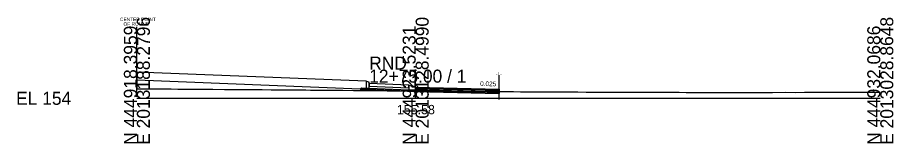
# Model space of a CAD drawing. Extents: x -26 to 163, y -10 to 7518.
# Drawn here: x -25.7 to 162.8, y 5490.3 to 5517.3 of the extents above; entities that cross this region are included whole.
import ezdxf

# ---------------------------------------------------------------- set-up
doc = ezdxf.new("R2010")
doc.units = 0
for name, color, linetype in [('Exist Cross Section Cell', 7, 'Continuous'), ('Exist XS Center Line Elevation Label', 7, 'Continuous'), ('Exist XS Ground Line', 7, 'Continuous'), ('Prop CMT Conc Surface', 7, 'Continuous'), ('Prop CMT Concrete Structures', 7, 'Continuous'), ('Prop CMT Pvmt Course 1', 7, 'Continuous'), ('Prop CMT Pvmt Course 1 CG', 7, 'Continuous'), ('Prop CMT Pvmt Course 2', 7, 'Continuous'), ('Prop CMT Pvmt Course 3', 7, 'Continuous'), ('Prop CMT Pvmt Surface', 7, 'Continuous'), ('Prop CMT Shear Line', 7, 'Continuous'), ('Prop CMT Shear Line Text', 7, 'Continuous'), ('Prop CMT Slope Grass', 7, 'Continuous'), ('Prop CMT Subgrade Earthwork', 7, 'Continuous'), ('Prop XS Earthwork Shape', 7, 'Continuous'), ('Prop XS SE Text', 7, 'Continuous')]:
    doc.layers.add(name, color=color, linetype=linetype)

msp = doc.modelspace()

# ---------------------------------------------------------------- linework, layer by layer
at = {"layer": 'Exist Cross Section Cell'}
for p, q in [((60, 5500), (60, 5506.16)), ((0, 5500), (60, 5500)), ((60, 5500), (160, 5500))]:
    msp.add_line(p, q, dxfattribs=at)
at = {"layer": 'Exist XS Ground Line'}
msp.add_lwpolyline([(0, 5502.05), (1.26, 5502.04), (2.71, 5502.03), (3.77, 5502.03), (5.03, 5502.02), (6.29, 5502.01), (7.37, 5502), (8.8, 5501.99), (10.5, 5501.98), (11.31, 5501.97), (13.27, 5501.96), (13.82, 5501.95), (16, 5501.94), (16.33, 5501.93), (18.83, 5501.92), (19.69, 5501.92), (21.51, 5501.9), (23.85, 5501.89), (25.84, 5501.87), (26.36, 5501.87), (26.98, 5501.86), (28.87, 5501.85), (29.73, 5501.84), (31.38, 5501.83), (32.47, 5501.82), (33.89, 5501.81), (35.06, 5501.8), (36.39, 5501.79), (37.39, 5501.78), (38.91, 5501.76), (39.7, 5501.76), (41.42, 5501.74), (42.01, 5501.74), (43.93, 5501.72), (44.33, 5501.72), (46.65, 5501.7), (49.08, 5501.68), (51.62, 5501.65), (53.85, 5501.63), (54.32, 5501.62), (56.29, 5501.61), (56.99, 5501.6), (58.74, 5501.59), (59.66, 5501.59), (60, 5501.58), (61.2, 5501.57), (62.33, 5501.56), (63.65, 5501.55), (64, 5501.54), (64.99, 5501.54), (66.11, 5501.53), (66.51, 5501.52), (67.43, 5501.52), (68.37, 5501.51), (69.02, 5501.51), (70.04, 5501.5), (70.82, 5501.49), (71.53, 5501.49), (72.64, 5501.48), (73.27, 5501.47), (74.04, 5501.47), (75.23, 5501.46), (75.72, 5501.46), (76.54, 5501.46), (77.82, 5501.44), (78.18, 5501.44), (78.91, 5501.44), (79.37, 5501.44), (80.64, 5501.43), (81.05, 5501.43), (82.54, 5501.42), (83.29, 5501.42), (84.45, 5501.42), (86.14, 5501.41), (86.72, 5501.41), (89.43, 5501.39), (91.68, 5501.37), (92.16, 5501.37), (94.18, 5501.36), (94.93, 5501.36), (96.68, 5501.35), (97.74, 5501.35), (99.28, 5501.34), (100.7, 5501.33), (101.75, 5501.33), (103.58, 5501.32), (104.21, 5501.32), (106.67, 5501.31), (107.31, 5501.31), (109.16, 5501.31), (111.33, 5501.31), (111.67, 5501.31), (112.08, 5501.31), (114.18, 5501.3), (115.94, 5501.29), (116.69, 5501.29), (118.25, 5501.28), (119.2, 5501.28), (119.87, 5501.28), (121.2, 5501.28), (121.71, 5501.28), (122.3, 5501.28), (123.77, 5501.28), (124.21, 5501.27), (124.72, 5501.27), (126.36, 5501.27), (126.73, 5501.27), (127.14, 5501.27), (129.24, 5501.27), (129.56, 5501.27), (131.54, 5501.27), (131.96, 5501.27), (134.37, 5501.27), (136.44, 5501.28), (136.79, 5501.28), (139.54, 5501.29), (141.79, 5501.28), (143.67, 5501.29), (144.29, 5501.3), (145.98, 5501.29), (146.8, 5501.3), (148.29, 5501.3), (149.3, 5501.3), (150.51, 5501.31), (151.82, 5501.31), (153.27, 5501.32), (154.33, 5501.32), (156.03, 5501.33), (156.84, 5501.33), (157.53, 5501.33), (159.34, 5501.34), (160, 5501.34)], dxfattribs=at)
at = {"layer": 'Prop CMT Conc Surface'}
for points in [[(50, 5503.35), (49.96, 5503.45), (49.85, 5503.49), (49.34, 5503.68)], [(50, 5503.18), (50, 5503.35)], [(60, 5502.39), (59.25, 5502.41), (59.25, 5502.57), (58.5, 5502.82)]]:
    msp.add_lwpolyline(points, dxfattribs=at)
at = {"layer": 'Prop CMT Concrete Structures'}
for points in [[(50, 5503.35), (49.96, 5503.45), (49.85, 5503.49), (49.34, 5503.68)], [(49.34, 5503.68), (49.34, 5502.18)], [(50, 5503.18), (50, 5503.35)], [(49.34, 5502.18), (50, 5502.18)], [(50, 5502.18), (50, 5503.18)], [(50, 5503.18), (50, 5502.6)], [(58.5, 5502.82), (50, 5503.16)], [(50, 5502.58), (58.5, 5502.24)], [(60, 5502.39), (59.25, 5502.41), (59.25, 5502.57), (58.5, 5502.82)], [(58.5, 5502.82), (58.5, 5501.84)], [(58.5, 5502.24), (58.5, 5502.82)], [(58.5, 5501.84), (60, 5501.8)], [(60, 5501.8), (60, 5502.39)]]:
    msp.add_lwpolyline(points, dxfattribs=at)
at = {"layer": 'Prop CMT Pvmt Course 1'}
for points in [[(60, 5502.39), (78, 5501.93)], [(60, 5502.14), (60, 5502.39)], [(78, 5501.68), (60, 5502.14)], [(78, 5501.93), (78, 5501.68)]]:
    msp.add_lwpolyline(points, dxfattribs=at)
msp.add_lwpolyline([(60, 5502.14), (60, 5502.26), (60, 5502.26), (60, 5502.14)], close=True, dxfattribs=at)
at = {"layer": 'Prop CMT Pvmt Course 1 CG'}
for points in [[(60, 5501.47), (60, 5501.8)], [(78, 5501.02), (78, 5501.35)]]:
    msp.add_lwpolyline(points, dxfattribs=at)
at = {"layer": 'Prop CMT Pvmt Course 2'}
for points in [[(60, 5501.8), (60, 5502.14)], [(60, 5502.14), (78, 5501.68)], [(78, 5501.35), (60, 5501.8)], [(78, 5501.68), (78, 5501.35)]]:
    msp.add_lwpolyline(points, dxfattribs=at)
at = {"layer": 'Prop CMT Pvmt Course 3'}
for points in [[(50, 5502.18), (58.5, 5501.84)], [(60, 5501.8), (78, 5501.35)], [(60, 5501.47), (60, 5501.8)], [(78, 5501.02), (60, 5501.47)], [(78, 5501.35), (78, 5501.02)]]:
    msp.add_lwpolyline(points, dxfattribs=at)
at = {"layer": 'Prop CMT Pvmt Surface'}
msp.add_lwpolyline([(60, 5502.39), (78, 5501.93)], dxfattribs=at)
at = {"layer": 'Prop CMT Shear Line'}
for p, q in [((0, 5500.33), (0, 5515.33)), ((78, 5499.76), (78, 5504.77))]:
    msp.add_line(p, q, dxfattribs=at)
at = {"layer": 'Prop CMT Slope Grass'}
for p, q in [((49.34, 5503.66), (0, 5505.64)), ((48.06, 5501.95), (0, 5503.87))]:
    msp.add_line(p, q, dxfattribs=at)
at = {"layer": 'Prop CMT Subgrade Earthwork'}
for p, q in [((0, 5505.64), (0, 5502.05)), ((48.34, 5502.22), (48.06, 5501.95)), ((78, 5501.93), (78, 5501.44)), ((78, 5501.02), (78, 5501.44))]:
    msp.add_line(p, q, dxfattribs=at)
for points in [[(48.06, 5501.95), (60, 5501.47)], [(48.34, 5502.22), (49.34, 5502.18)], [(60, 5501.47), (78, 5501.02)]]:
    msp.add_lwpolyline(points, dxfattribs=at)
at = {"layer": 'Prop XS Earthwork Shape'}
for points in [[(36.39, 5501.79), (37.39, 5501.78), (38.91, 5501.76), (39.7, 5501.76), (41.42, 5501.74), (42.01, 5501.74), (43.93, 5501.72), (44.33, 5501.72), (46.65, 5501.7), (49.08, 5501.68), (51.62, 5501.65), (53.85, 5501.63), (54.32, 5501.62), (56.29, 5501.61), (56.57, 5501.61), (48.06, 5501.95), (0, 5503.87), (0, 5502.05), (1.26, 5502.04), (2.71, 5502.03), (3.77, 5502.03), (5.03, 5502.02), (6.29, 5502.01), (7.37, 5502), (8.8, 5501.99), (10.5, 5501.98), (11.31, 5501.97), (13.27, 5501.96), (13.82, 5501.95), (16, 5501.94), (16.33, 5501.93), (18.83, 5501.92), (19.69, 5501.92), (21.51, 5501.9), (23.85, 5501.89), (25.84, 5501.87), (26.36, 5501.87), (26.98, 5501.86), (28.87, 5501.85), (29.73, 5501.84), (31.38, 5501.83), (32.47, 5501.82), (33.89, 5501.81), (35.06, 5501.8)], [(56.99, 5501.6), (58.74, 5501.59), (59.66, 5501.59), (60, 5501.58), (61.2, 5501.57), (62.33, 5501.56), (63.65, 5501.55), (64, 5501.54), (64.99, 5501.54), (66.11, 5501.53), (66.51, 5501.52), (67.43, 5501.52), (68.37, 5501.51), (69.02, 5501.51), (70.04, 5501.5), (70.82, 5501.49), (71.53, 5501.49), (72.64, 5501.48), (73.27, 5501.47), (74.04, 5501.47), (75.23, 5501.46), (75.72, 5501.46), (76.54, 5501.46), (77.82, 5501.44), (78, 5501.44), (78, 5501.02), (60, 5501.47), (56.57, 5501.61)]]:
    msp.add_lwpolyline(points, close=True, dxfattribs=at)

# ---------------------------------------------------------------- texts
at = {"layer": 'Exist Cross Section Cell'}
for s, p in [('E 2013188.2796', (2.8, 5490)), ('E 2013128.4990', (62.8, 5490)), ('E 2013028.8648', (162.8, 5490)), ('N 444918.3959', (0, 5490)), ('N 444923.5231', (60, 5490)), ('N 444932.0686', (160, 5490))]:
    msp.add_text(s, height=2.8, rotation=90, dxfattribs=at).set_placement(p)
for s, p in [('RND', (50, 5506.16)), ('12+75.00 / 1', (50, 5503.36)), ('EL 154', (-26, 5498.6))]:
    msp.add_text(s, height=2.8, dxfattribs=at).set_placement(p)
at = {"layer": 'Exist XS Center Line Elevation Label'}
msp.add_text('155.58', height=2, dxfattribs=at).set_placement((55.96, 5496.58))
at = {"layer": 'Prop CMT Shear Line Text'}
for s, p in [('CENTER POINT', (-3.64, 5516.58)), ('OF ROUND', (-2.88, 5515.6)), ('-L-', (77.27, 5504.89))]:
    msp.add_text(s, height=0.75, dxfattribs=at).set_placement(p)
at = {"layer": 'Prop XS SE Text'}
msp.add_text('0.025', height=1, rotation=358.5613, dxfattribs=at).set_placement((73.87, 5502.66))

doc.saveas('drawing.dxf')
